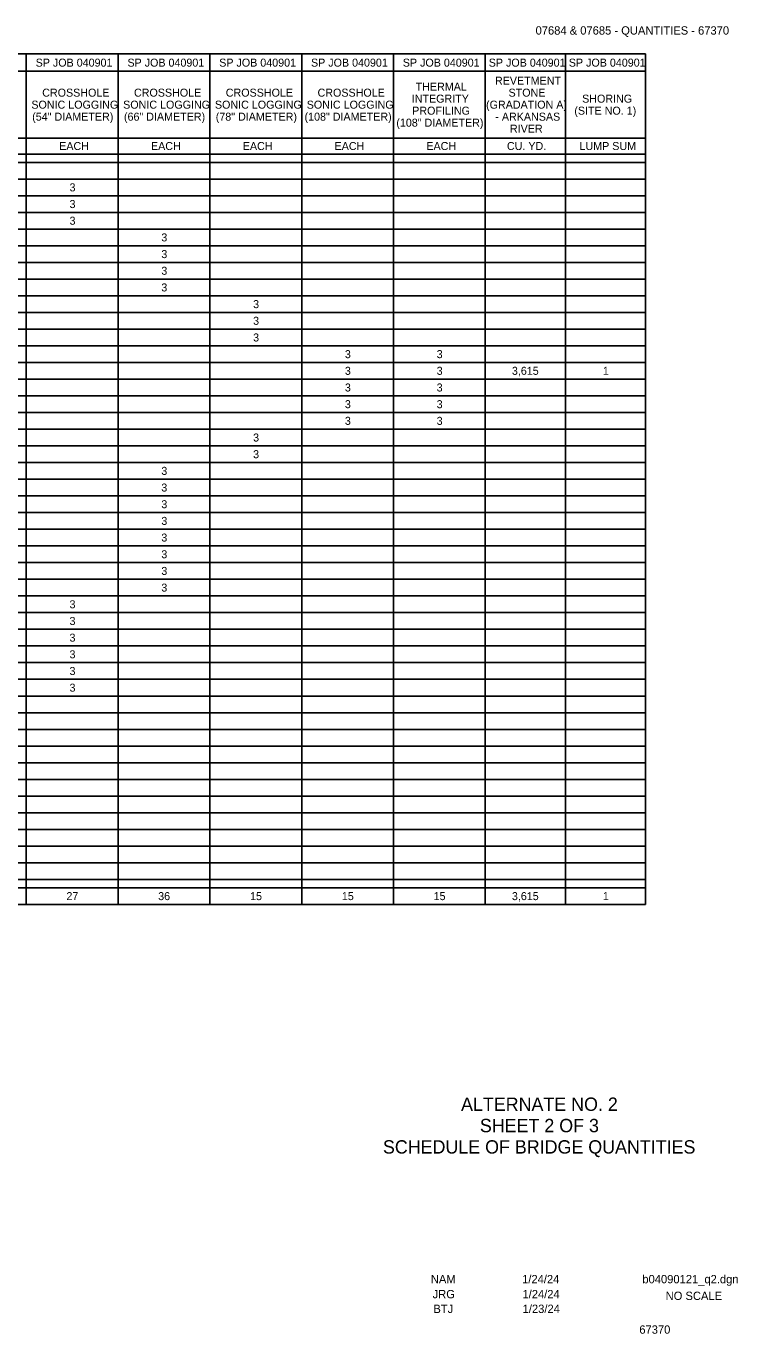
# Model space of a CAD drawing. Extents: x 0.06 to 1.36, y 0.04 to 0.85.
# Drawn here: x 0.914 to 1.358, y 0.037 to 0.854 of the extents above; entities that cross this region are included whole.
import ezdxf

# ---------------------------------------------------------------- set-up
doc = ezdxf.new("R2010")
doc.units = 0
doc.layers.add('R_Shade By Others', color=7, linetype='Continuous')
doc.layers.add('R_Survey Control', color=7, linetype='Continuous')

msp = doc.modelspace()

# ---------------------------------------------------------------- linework, layer by layer
at = {"layer": 'R_Survey Control'}
for p, q in [((0.07508, 0.83695), (1.30054, 0.83695)), ((0.9141, 0.83695), (0.9141, 0.3057)), ((0.97139, 0.83695), (0.97139, 0.3057)), ((1.02868, 0.83695), (1.02868, 0.3057)), ((1.08598, 0.83695), (1.08598, 0.3057)), ((1.14327, 0.83695), (1.14327, 0.3057)), ((1.20056, 0.83695), (1.20056, 0.3057)), ((1.25055, 0.83695), (1.25055, 0.3057)), ((1.30054, 0.83695), (1.30054, 0.3057)), ((0.2593, 0.78445), (1.30054, 0.78445)), ((0.07508, 0.77445), (1.30054, 0.77445)), ((0.11154, 0.76924), (1.30054, 0.76924)), ((0.11154, 0.75883), (1.30054, 0.75883)), ((0.11154, 0.74841), (1.30054, 0.74841)), ((0.11154, 0.73799), (1.30054, 0.73799)), ((0.11154, 0.72758), (1.30054, 0.72758)), ((0.11154, 0.71716), (1.30054, 0.71716)), ((0.11154, 0.70674), (1.30054, 0.70674)), ((0.11154, 0.69633), (1.30054, 0.69633)), ((0.11154, 0.68591), (1.30054, 0.68591)), ((0.11154, 0.67549), (1.30054, 0.67549)), ((0.11154, 0.66508), (1.30054, 0.66508)), ((0.11154, 0.65466), (1.30054, 0.65466)), ((0.11154, 0.64424), (1.30054, 0.64424)), ((0.11154, 0.63383), (1.30054, 0.63383)), ((0.11154, 0.62341), (1.30054, 0.62341)), ((0.11154, 0.61299), (1.30054, 0.61299)), ((0.11154, 0.60258), (1.30054, 0.60258)), ((0.11154, 0.59216), (1.30054, 0.59216)), ((0.11154, 0.58174), (1.30054, 0.58174)), ((0.11154, 0.57133), (1.30054, 0.57133)), ((0.11154, 0.56091), (1.30054, 0.56091)), ((0.11154, 0.55049), (1.30054, 0.55049)), ((0.11154, 0.54008), (1.30054, 0.54008)), ((0.11154, 0.52966), (1.30054, 0.52966)), ((0.11154, 0.51924), (1.30054, 0.51924)), ((0.11154, 0.50883), (1.30054, 0.50883)), ((0.11154, 0.49841), (1.30054, 0.49841)), ((0.11154, 0.48799), (1.30054, 0.48799)), ((0.11154, 0.47758), (1.30054, 0.47758)), ((0.11154, 0.46716), (1.30054, 0.46716)), ((0.11154, 0.45674), (1.30054, 0.45674)), ((0.11154, 0.44633), (1.30054, 0.44633)), ((0.11154, 0.43591), (1.30054, 0.43591)), ((0.11154, 0.42549), (1.30054, 0.42549)), ((0.11154, 0.41508), (1.30054, 0.41508)), ((0.11154, 0.40466), (1.30054, 0.40466)), ((0.11154, 0.39424), (1.30054, 0.39424)), ((0.11154, 0.38383), (1.30054, 0.38383)), ((0.11154, 0.37341), (1.30054, 0.37341)), ((0.11154, 0.36299), (1.30054, 0.36299)), ((0.11154, 0.35258), (1.30054, 0.35258)), ((0.11154, 0.34216), (1.30054, 0.34216)), ((0.11154, 0.33174), (1.30054, 0.33174)), ((0.11154, 0.32133), (1.30054, 0.32133)), ((0.07508, 0.31612), (1.30054, 0.31612)), ((0.07508, 0.3057), (1.30054, 0.3057))]:
    msp.add_line(p, q, dxfattribs=at)
msp.add_lwpolyline([(0.2593, 0.82612), (0.30758, 0.82612), (0.36154, 0.82612), (0.40321, 0.82612), (0.44487, 0.82612), (0.49175, 0.82612), (0.52821, 0.82612), (0.58029, 0.82612), (0.64019, 0.82612), (0.7079, 0.82612), (0.75998, 0.82612), (0.81206, 0.82612), (0.85894, 0.82612), (0.86623, 0.82612), (0.92873, 0.82612), (0.99644, 0.82612), (1.06415, 0.82612), (1.11623, 0.82612), (1.16831, 0.82612), (1.30054, 0.82612)], dxfattribs=at)

# ---------------------------------------------------------------- texts
at = {"layer": 'R_Shade By Others'}
for s, height, p in [('07684 & 07685 - QUANTITIES - 67370', 0.0052083, (1.23197, 0.84904)), ('ALTERNATE NO. 2', 0.0083332, (1.18545, 0.17677)), ('SHEET 2 OF 3', 0.0083332, (1.1972, 0.16344)), ('SCHEDULE OF BRIDGE QUANTITIES', 0.0083332, (1.13669, 0.1501)), ('NAM', 0.005208, (1.1666, 0.06906)), ('1/24/24', 0.005208, (1.22357, 0.06906)), ('b04090121_q2.dgn', 0.0052083, (1.29862, 0.06906)), ('JRG', 0.005208, (1.1677, 0.05969)), ('1/24/24', 0.005208, (1.22378, 0.05969)), ('NO SCALE', 0.005208, (1.31316, 0.05864)), ('BTJ', 0.005208, (1.16819, 0.05052)), ('1/23/24', 0.005208, (1.22389, 0.05052)), ('67370', 0.005208, (1.29672, 0.03756))]:
    msp.add_text(s, height=height, dxfattribs=at).set_placement(p)
at = {"layer": 'R_Survey Control'}
for s, p in [('SP JOB 040901', (0.91992, 0.82904)), ('SP JOB 040901', (0.97721, 0.82904)), ('SP JOB 040901', (1.0345, 0.82904)), ('SP JOB 040901', (1.09179, 0.82904)), ('SP JOB 040901', (1.14909, 0.82904)), ('SP JOB 040901', (1.20273, 0.82904)), ('SP JOB 040901', (1.25271, 0.82904)), ('THERMAL', (1.15711, 0.81404)), ('REVETMENT', (1.20662, 0.81779)), ('CROSSHOLE', (0.92401, 0.81029)), ('CROSSHOLE', (0.9813, 0.81029)), ('CROSSHOLE', (1.03859, 0.81029)), ('CROSSHOLE', (1.09588, 0.81029)), ('INTEGRITY', (1.15468, 0.80654)), ('STONE', (1.21509, 0.81029)), ('SHORING', (1.26103, 0.80654)), ('SONIC LOGGING', (0.91724, 0.80279)), ('(54" DIAMETER)', (0.91776, 0.79529)), ('SONIC LOGGING', (0.97453, 0.80279)), ('(66" DIAMETER)', (0.97505, 0.79529)), ('SONIC LOGGING', (1.03182, 0.80279)), ('(78" DIAMETER)', (1.03235, 0.79529)), ('(108" DIAMETER)', (1.08776, 0.79529)), ('SONIC LOGGING', (1.08912, 0.80279)), ('PROFILING', (1.15496, 0.79904)), ('(GRADATION A)', (1.20106, 0.80279)), ('(SITE NO. 1)', (1.25616, 0.79904)), ('(108" DIAMETER)', (1.14505, 0.79154)), ('- ARKANSAS', (1.20685, 0.79529)), ('RIVER', (1.21597, 0.78779)), ('EACH', (0.93462, 0.77695)), ('EACH', (0.99191, 0.77695)), ('EACH', (1.04921, 0.77695)), ('EACH', (1.1065, 0.77695)), ('EACH', (1.16379, 0.77695)), ('CU. YD.', (1.21409, 0.77695)), ('LUMP SUM', (1.25939, 0.77695)), ('3', (0.94107, 0.75112)), ('3', (0.94107, 0.7407)), ('3', (0.94107, 0.73029)), ('3', (0.99836, 0.71987)), ('3', (0.99836, 0.70945)), ('3', (0.99836, 0.69904)), ('3', (0.99836, 0.68862)), ('3', (1.05565, 0.6782)), ('3', (1.05565, 0.66779)), ('3', (1.05565, 0.65737)), ('3', (1.11294, 0.64695)), ('3', (1.17023, 0.64695)), ('3', (1.11294, 0.63654)), ('3', (1.17023, 0.63654)), ('3,615', (1.21719, 0.63654)), ('1', (1.27394, 0.63654)), ('3', (1.11294, 0.62612)), ('3', (1.17023, 0.62612)), ('3', (1.11294, 0.6157)), ('3', (1.17023, 0.6157)), ('3', (1.11294, 0.60529)), ('3', (1.17023, 0.60529)), ('3', (1.05565, 0.59487)), ('3', (1.05565, 0.58445)), ('3', (0.99836, 0.57404)), ('3', (0.99836, 0.56362)), ('3', (0.99836, 0.5532)), ('3', (0.99836, 0.54279)), ('3', (0.99836, 0.53237)), ('3', (0.99836, 0.52195)), ('3', (0.99836, 0.51154)), ('3', (0.99836, 0.50112)), ('3', (0.94107, 0.4907)), ('3', (0.94107, 0.48029)), ('3', (0.94107, 0.46987)), ('3', (0.94107, 0.45945)), ('3', (0.94107, 0.44904)), ('3', (0.94107, 0.43862)), ('27', (0.93912, 0.30841)), ('36', (0.9964, 0.30841)), ('15', (1.05376, 0.30841)), ('15', (1.11105, 0.30841)), ('15', (1.16834, 0.30841)), ('3,615', (1.21719, 0.30841)), ('1', (1.27394, 0.30841))]:
    msp.add_text(s, height=0.005, dxfattribs=at).set_placement(p)

doc.saveas('drawing.dxf')
